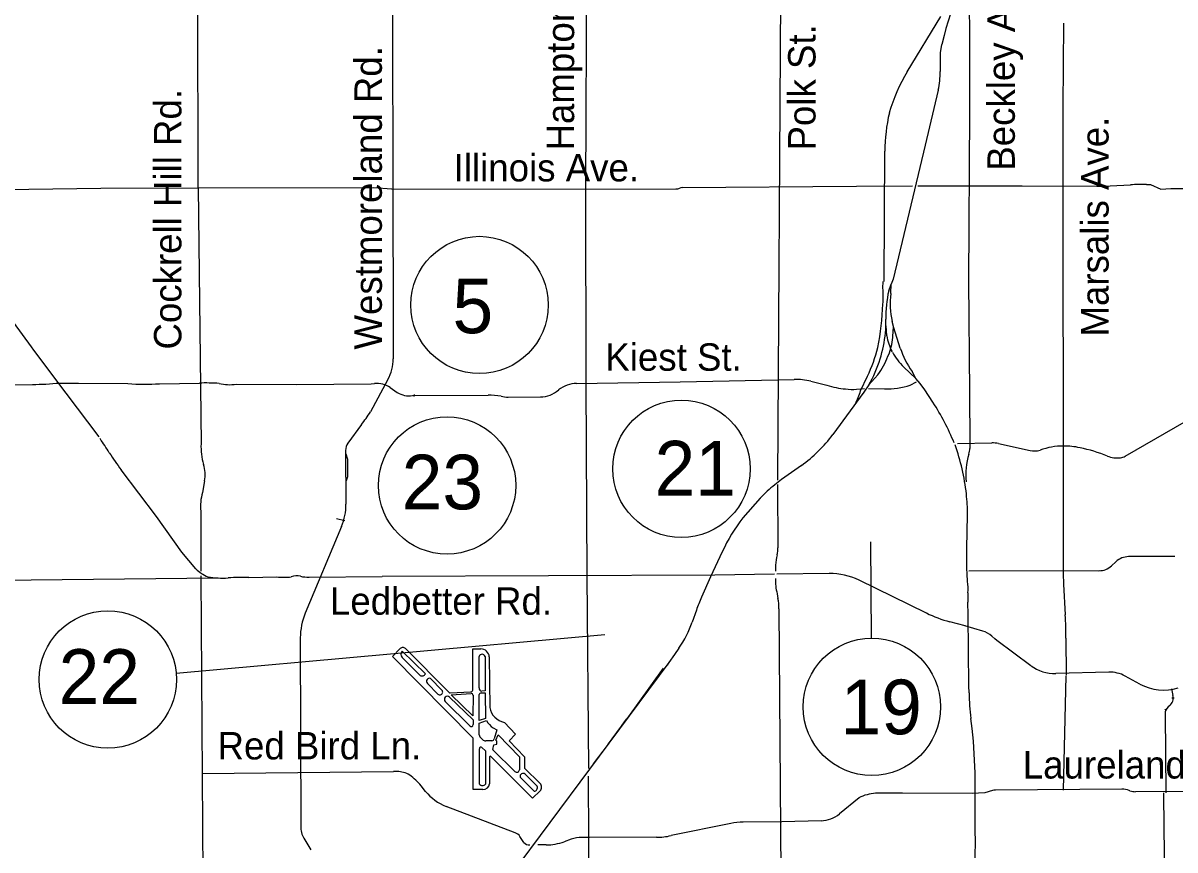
# Model space of a CAD drawing. Extents: x 105094 to 105814, y -291615 to -291123.
# Drawn here: x 105395.2 to 105446.1, y -291530.7 to -291494.1 of the extents above; entities that cross this region are included whole.
import ezdxf

# ---------------------------------------------------------------- set-up
doc = ezdxf.new("R2010")
doc.units = 0
doc.layers.add('G_BORDER', color=7, linetype='Continuous')
doc.layers.add('G_MAP', color=7, linetype='Continuous')

msp = doc.modelspace()

# ---------------------------------------------------------------- linework, layer by layer
at = {"layer": 'G_BORDER'}
for p, q in [((105432.632, -291517.07), (105432.669, -291521.335)), ((105420.896, -291521.192), (105401.969, -291522.889))]:
    msp.add_line(p, q, dxfattribs=at)
for centre in [(105415.362, -291506.606), (105424.284, -291513.846), (105413.931, -291514.582), (105398.946, -291523.16), (105432.696, -291524.37)]:
    msp.add_circle(centre, 3.035, dxfattribs=at)
at = {"layer": 'G_MAP'}
for p, q in [((105428.684, -291489.722), (105428.529, -291514.353)), ((105402.905, -291491.656), (105402.928, -291501.409)), ((105434.261, -291496.294), (105435.744, -291493.849)), ((105436.176, -291493.74), (105435.97, -291494.385)), ((105435.779, -291495.093), (105435.721, -291495.454)), ((105435.721, -291495.454), (105435.714, -291495.734)), ((105435.629, -291497.104), (105435.056, -291499.543)), ((105433.247, -291505.572), (105433.272, -291499.814)), ((105435.056, -291499.543), (105433.632, -291505.459)), ((105402.931, -291501.409), (105403.064, -291512.751)), ((105411.499, -291501.48), (105424.035, -291501.477)), ((105443.227, -291501.342), (105444.128, -291501.297)), ((105444.835, -291501.277), (105445.014, -291501.282)), ((105393.398, -291505.54), (105395.562, -291508.449)), ((105433.189, -291505.866), (105433.196, -291505.572)), ((105433.632, -291505.459), (105433.557, -291505.685)), ((105433.443, -291505.979), (105433.557, -291505.685)), ((105433.531, -291506.105), (105433.557, -291505.685)), ((105433.364, -291507.963), (105433.331, -291507.529)), ((105411.548, -291507.862), (105411.551, -291508.988)), ((105395.555, -291508.459), (105395.662, -291508.598)), ((105395.662, -291508.598), (105397.089, -291510.497)), ((105433.47, -291508.718), (105433.573, -291508.349)), ((105433.602, -291508.686), (105433.564, -291508.618)), ((105433.41, -291508.876), (105433.47, -291508.718)), ((105434.639, -291509.851), (105434.103, -291509.354)), ((105434.639, -291509.851), (105434.473, -291509.543)), ((105388.283, -291510.206), (105395.62, -291510.118)), ((105401.233, -291510.09), (105402.988, -291510.056)), ((105411.32, -291509.9), (105410.543, -291511.333)), ((105410.585, -291510.09), (105410.727, -291510.078)), ((105430.001, -291509.979), (105430.712, -291510.155)), ((105432.201, -291510.407), (105432.507, -291509.753)), ((105432.569, -291510.142), (105432.343, -291510.458)), ((105432.569, -291510.142), (105432.962, -291509.692)), ((105434.397, -291510.152), (105434.675, -291509.996)), ((105434.83, -291510.084), (105434.639, -291509.851)), ((105397.089, -291510.497), (105398.546, -291512.441)), ((105411.418, -291510.259), (105411.732, -291510.471)), ((105412.41, -291510.61), (105415.741, -291510.591)), ((105412.475, -291510.568), (105412.471, -291510.658)), ((105416.636, -291510.679), (105418.059, -291510.671)), ((105432.343, -291510.458), (105430.972, -291512.332)), ((105432.021, -291510.329), (105432.372, -291510.303)), ((105432.543, -291510.3), (105433.257, -291510.31)), ((105437.013, -291510.468), (105437.026, -291512.729)), ((105410.149, -291511.892), (105409.55, -291512.72)), ((105436.483, -291512.729), (105437.995, -291512.705)), ((105409.447, -291513.034), (105409.467, -291515.407)), ((105437.026, -291512.729), (105437.026, -291512.948)), ((105438.285, -291512.734), (105439.685, -291513.039)), ((105429.583, -291513.705), (105428.713, -291514.327)), ((105403.218, -291514.38), (105403.122, -291514.899)), ((105428.713, -291514.327), (105428.409, -291514.56)), ((105428.529, -291514.547), (105428.549, -291517.34)), ((105427.77, -291515.143), (105427.005, -291516.016)), ((105403.051, -291515.719), (105403.058, -291518.367)), ((105409.048, -291516.042), (105409.41, -291516.139)), ((105409.273, -291516.398), (105407.669, -291520.23)), ((105426.086, -291517.522), (105425.574, -291518.625)), ((105446.088, -291517.721), (105444.039, -291517.731)), ((105428.445, -291518.11), (105428.445, -291518.37)), ((105436.907, -291518.493), (105436.9, -291518.261)), ((105443.48, -291517.953), (105443.284, -291518.135)), ((105394.157, -291518.774), (105403.813, -291518.671)), ((105403.058, -291518.577), (105403.252, -291547.706)), ((105405.176, -291518.654), (105406.413, -291518.629)), ((105407.838, -291518.636), (105411.063, -291518.603)), ((105425.755, -291518.554), (105411.063, -291518.603)), ((105425.574, -291518.625), (105425.174, -291519.524)), ((105428.393, -291518.509), (105425.755, -291518.554)), ((105430.816, -291518.477), (105428.493, -291518.506)), ((105435.105, -291520.222), (105432.132, -291518.772)), ((105436.919, -291518.823), (105436.907, -291518.493)), ((105442.732, -291518.354), (105436.984, -291518.374)), ((105441.17, -291518.952), (105441.234, -291520.308)), ((105428.516, -291519.368), (105428.545, -291519.575)), ((105436.945, -291520.308), (105436.935, -291519.748)), ((105424.946, -291520.1), (105424.762, -291520.625)), ((105436.987, -291523.437), (105436.958, -291520.321)), ((105436.813, -291520.793), (105436.147, -291520.613)), ((105437.604, -291521.023), (105436.811, -291520.794)), ((105407.446, -291521.317), (105407.466, -291529.651)), ((105438.124, -291521.361), (105437.992, -291521.24)), ((105438.221, -291521.435), (105438.124, -291521.361)), ((105441.263, -291521.335), (105441.276, -291522.972)), ((105411.528, -291522.142), (105411.86, -291521.795)), ((105412.093, -291521.793), (105414.007, -291523.726)), ((105439.727, -291522.554), (105438.221, -291521.435)), ((105411.934, -291521.923), (105411.948, -291521.906)), ((105412.715, -291522.957), (105411.945, -291522.182)), ((105415.349, -291523.53), (105415.346, -291522.14)), ((105415.611, -291522.146), (105415.62, -291523.667)), ((105415.795, -291522.162), (105415.817, -291524.396)), ((105423.73, -291522.407), (105413.909, -291535.612)), ((105423.484, -291522.665), (105421.873, -291524.894)), ((105443.164, -291522.836), (105440.825, -291522.901)), ((105413.53, -291523.807), (105413.065, -291523.333)), ((105413.205, -291523.114), (105413.704, -291523.638)), ((105441.267, -291522.992), (105441.154, -291528.059)), ((105444.54, -291523.361), (105443.891, -291523.01)), ((105414.073, -291523.751), (105414.988, -291523.701)), ((105415.078, -291523.859), (105415.075, -291524.774)), ((105415.62, -291523.667), (105415.467, -291523.675)), ((105436.991, -291523.757), (105436.987, -291523.437)), ((105445.933, -291523.57), (105446, -291523.871)), ((105414.932, -291525.216), (105413.853, -291524.131)), ((105414.04, -291523.942), (105415.078, -291524.949)), ((105445.853, -291524.318), (105445.79, -291524.372)), ((105446.053, -291523.983), (105445.956, -291523.99)), ((105437.133, -291525.333), (105437.072, -291524.88)), ((105445.72, -291524.529), (105445.633, -291524.487)), ((105445.648, -291524.68), (105445.681, -291528.165)), ((105415.078, -291524.949), (105415.078, -291525.157)), ((105415.966, -291525.304), (105416.137, -291525.381)), ((105416.137, -291525.381), (105416.019, -291525.787)), ((105415.497, -291525.811), (105415.386, -291525.689)), ((105415.914, -291525.868), (105415.65, -291525.876)), ((105415.359, -291527.781), (105415.359, -291526.22)), ((105415.474, -291526.172), (105415.627, -291526.321)), ((105415.627, -291526.321), (105415.63, -291527.794)), ((105416.927, -291527.228), (105415.969, -291526.286)), ((105421.046, -291526.021), (105420.387, -291526.896)), ((105415.811, -291526.608), (105415.805, -291527.767)), ((105403.116, -291527.319), (105411.564, -291527.229)), ((105411.723, -291527.229), (105411.564, -291527.229)), ((105417.38, -291527.347), (105417.917, -291527.881)), ((105412.986, -291528.111), (105412.785, -291527.861)), ((105417.775, -291528.104), (105417.164, -291527.484)), ((105437.265, -291528.246), (105437.265, -291527.574)), ((105432.13, -291528.395), (105431.262, -291529.105)), ((105434.058, -291528.185), (105432.863, -291528.188)), ((105437.136, -291528.194), (105434.058, -291528.185)), ((105437.265, -291530.006), (105437.265, -291528.246)), ((105443.746, -291528.013), (105438.16, -291528.05)), ((105444.1, -291528.078), (105444.067, -291528.067)), ((105448.589, -291528.101), (105444.347, -291528.12)), ((105416.944, -291529.932), (105413.89, -291528.768)), ((105428.723, -291529.454), (105427.014, -291529.463)), ((105430.454, -291529.406), (105428.723, -291529.454)), ((105426.469, -291529.531), (105423.827, -291530.058)), ((105407.605, -291530.18), (105407.911, -291530.697)), ((105417.327, -291530.362), (105417.153, -291530.098)), ((105418.305, -291530.471), (105417.943, -291530.471)), ((105419.414, -291530.22), (105419.106, -291530.331)), ((105420.229, -291530.142), (105419.895, -291530.138)), ((105423.181, -291530.129), (105420.229, -291530.142))]:
    msp.add_line(p, q, dxfattribs=at)
for points in [[(105411.418, -291484.332), (105411.509, -291487.671), (105411.548, -291507.862)], [(105420.038, -291485.259), (105420.086, -291487.387), (105420.086, -291491.595), (105420.048, -291501.487), (105420.061, -291510.045), (105420.113, -291518.574), (105420.181, -291527.093)], [(105436.948, -291489.541), (105436.948, -291490.972), (105436.971, -291493.09), (105437.006, -291494.166), (105437.006, -291494.818), (105437.01, -291498.067), (105436.971, -291505.559), (105437.013, -291510.468)], [(105435.97, -291494.385), (105435.895, -291494.689), (105435.782, -291495.093)], [(105441.164, -291494.142), (105441.14, -291497.86), (105441.15, -291518.183)], [(105411.499, -291501.48), (105410.689, -291501.429), (105402.938, -291501.448), (105398.63, -291501.464), (105394.402, -291501.522), (105386.9, -291501.593)], [(105424.313, -291501.42), (105432.023, -291501.348), (105434.487, -291501.342)], [(105434.733, -291501.342), (105439.338, -291501.342), (105442.632, -291501.358)], [(105445.014, -291501.282), (105445.462, -291501.487), (105445.901, -291501.464)], [(105445.901, -291501.464), (105446.925, -291501.452), (105448.049, -291501.444)], [(105433.953, -291508.511), (105433.674, -291507.62), (105433.59, -291507.332)], [(105396.831, -291510.067), (105397.645, -291510.067), (105399.831, -291510.083)], [(105404.614, -291510.109), (105407.285, -291510.116), (105410.585, -291510.09)], [(105419.652, -291510.073), (105424.23, -291510), (105429.267, -291509.897)], [(105435.395, -291510.909), (105435.037, -291510.361), (105434.83, -291510.084)], [(105443.89, -291513.291), (105448.72, -291510.51), (105449.989, -291509.735)], [(105409.491, -291514.366), (105409.552, -291514.182), (105409.555, -291513.436), (105409.478, -291513.2)], [(105402.828, -291518.267), (105402.215, -291517.537), (105401.091, -291515.955), (105399.536, -291513.894)], [(105436.9, -291518.261), (105436.9, -291517.376), (105436.921, -291515.881)], [(105428.587, -291520.04), (105428.713, -291535.628), (105428.736, -291543.637), (105428.72, -291546.744)], [(105415.074, -291523.597), (105415.065, -291521.806), (105415.421, -291521.806)], [(105424.17, -291521.775), (105423.972, -291522.055), (105423.73, -291522.407), (105423.656, -291522.523)], [(105415.515, -291528.03), (105415.091, -291528.03), (105415.087, -291525.756), (105411.528, -291522.142)], [(105411.948, -291521.906), (105412.985, -291522.904), (105412.954, -291522.944)], [(105415.075, -291524.774), (105414.115, -291523.841), (105414.995, -291523.778)], [(105415.637, -291524.878), (105415.349, -291524.978), (105415.346, -291523.828)], [(105415.441, -291523.757), (105415.62, -291523.754), (105415.637, -291524.878)], [(105415.356, -291525.604), (105415.352, -291525.097), (105415.678, -291524.974)], [(105416.463, -291525.055), (105416.951, -291525.575), (105416.68, -291525.879), (105417.358, -291526.576), (105417.355, -291527.087), (105418.039, -291527.755)], [(105415.96, -291526.257), (105415.998, -291526.056), (105416.124, -291526.021), (105416.127, -291525.882), (105416.092, -291525.846), (105416.195, -291525.604)], [(105416.195, -291525.604), (105417.132, -291526.576), (105417.126, -291527.151)], [(105418.04, -291528.083), (105417.703, -291528.414), (105415.868, -291526.559)], [(105420.297, -291545.217), (105420.265, -291544.225), (105420.181, -291527.435)], [(105438.021, -291528.072), (105437.695, -291528.178), (105437.136, -291528.194)], [(105445.711, -291535.419), (105445.701, -291532.993), (105445.646, -291531.886), (105445.61, -291529.719), (105445.601, -291528.165)]]:
    msp.add_lwpolyline(points, dxfattribs=at)
for centre, radius, start, end in [((105447.982, -291496.012), 12.271, 178.7008, 181.2855), ((105440.56, -291500.113), 7.367, 148.7734, 164.2625), ((105432.488, -291496.364), 3.228, 346.7609, 1.3625), ((105440.758, -291499.824), 7.485, 166.8045, 179.9189), ((105424.038, -291500.988), 0.489, 269.6178, 291.7942), ((105424.315, -291501.639), 0.219, 90.6234, 115.9105), ((105442.781, -291495.888), 5.472, 268.4408, 274.6687), ((105444.685, -291508.719), 7.444, 88.8439, 94.292), ((105425.618, -291506.182), 7.578, 357.087, 2.3875), ((105438.781, -291507.17), 5.47, 167.4298, 180.689), ((105437.34, -291506.54), 3.833, 173.4908, 191.9344), ((105419.886, -291505.99), 13.312, 349.2107, 357.5159), ((105429.85, -291507.5), 3.472, 354.3975, 4.3771), ((105429.397, -291507.558), 4.251, 349.2674, 0.3861), ((105424.71, -291506.682), 8.672, 344.5535, 352.334), ((105435.404, -291507.692), 2.058, 187.5488, 207.7788), ((105425.894, -291506.66), 7.3, 334.9346, 345.55), ((105437.357, -291507.443), 3.567, 197.4174, 216.0568), ((105409.637, -291508.988), 1.914, 331.5403, 0.0101), ((105426.513, -291506.821), 6.907, 331.2632, 341.6793), ((105430.236, -291507.666), 3.396, 323.3824, 339.1343), ((105436.418, -291507.097), 3.233, 209.432, 224.2744), ((105395.438, -291495.763), 14.357, 270.7286, 275.4652), ((105400.586, -291498.341), 11.766, 266.3213, 273.1505), ((105403.228, -291522.098), 12.044, 86.9672, 91.14), ((105404.338, -291508.176), 1.953, 255.9652, 278.1126), ((105410.817, -291511.146), 1.072, 55.8818, 94.8346), ((105419.673, -291511.374), 1.301, 90.938, 128.5797), ((105429.324, -291512.72), 2.823, 76.1233, 91.1639), ((105431.866, -291506.525), 3.809, 252.3603, 265.02), ((105433.39, -291507.083), 3.229, 267.6362, 288.167), ((105412.253, -291509.652), 0.971, 237.539, 279.3173), ((105415.76, -291514.063), 3.472, 80.7583, 90.3095), ((105416.65, -291509.372), 1.307, 255.2579, 269.3639), ((105418.052, -291509.443), 1.229, 270.3001, 290.4566), ((105417.656, -291508.842), 1.936, 295.2478, 308.5319), ((105431.833, -291507.617), 2.719, 263.7139, 273.9614), ((105427.614, -291508.878), 4.835, 334.3285, 341.5711), ((105426.75, -291516.573), 10.336, 21.9726, 33.2322), ((105406.092, -291508.613), 5.217, 321.0516, 328.5656), ((105384.28, -291522.224), 17.307, 31.664, 34.1344), ((105409.987, -291513.036), 0.54, 144.1258, 179.7639), ((105426.002, -291508.694), 6.159, 305.5528, 323.8053), ((105438.015, -291513.977), 1.272, 77.7063, 90.902), ((105409.018, -291506.742), 11.877, 212.5849, 217.0228), ((105405.746, -291512.876), 2.685, 177.3279, 196.8598), ((105427.432, -291515.994), 9.499, 6.2854, 19.7309), ((105440.328, -291514.143), 3.478, 164.2154, 184.5783), ((105435.747, -291512.847), 1.283, 344.1791, 355.4858), ((105439.872, -291512.28), 0.781, 256.1122, 289.0947), ((105441.179, -291516.053), 3.211, 90.2318, 109.1124), ((105441.176, -291516.34), 3.498, 78.1706, 90.1563), ((105440.444, -291519.833), 7.067, 67.9135, 78.1671), ((105401.724, -291514.103), 1.52, 349.4871, 17.1218), ((105443.531, -291512.237), 1.132, 247.6973, 277.8604), ((105443.628, -291512.835), 0.526, 275.9221, 299.8681), ((105431.51, -291518.599), 5.092, 127.5147, 137.2643), ((105405.377, -291515.507), 2.336, 164.8993, 185.1997), ((105429.707, -291515.78), 7.214, 359.1969, 6.5775), ((105406.967, -291515.432), 2.5, 337.2751, 0.5684), ((105432.855, -291520.617), 7.443, 141.8157, 155.4232), ((105430.803, -291518.22), 2.36, 165.9588, 177.3396), ((105427.39, -291517.359), 1.159, 345.6001, 0.9081), ((105444.043, -291518.557), 0.826, 90.2854, 132.9841), ((105404.108, -291516.918), 1.86, 226.5115, 246.4272), ((105449.687, -291518.352), 8.539, 178.8649, 184.0257), ((105442.729, -291517.54), 0.814, 270.2071, 312.9887), ((105404.03, -291514.577), 4.1, 260.6501, 273.2682), ((105404.913, -291530.003), 11.352, 88.6714, 93.2762), ((105406.714, -291515.59), 3.054, 264.3433, 276.2411), ((105407.3, -291519.371), 0.787, 78.6655, 108.7984), ((105407.813, -291516.92), 1.716, 257.9405, 270.8348), ((105430.408, -291518.828), 1.968, 176.0781, 195.9399), ((105430.853, -291521.394), 2.917, 63.998, 90.7255), ((105434.526, -291519.194), 2.423, 356.629, 8.8163), ((105442.378, -291519.656), 5.443, 176.6374, 180.9703), ((105431.996, -291522.561), 7.467, 156.0015, 160.756), ((105427.493, -291519.904), 1.102, 352.9326, 17.3848), ((105410.332, -291521.344), 2.886, 157.306, 179.4689), ((105437.681, -291514.937), 5.879, 244.0098, 254.8703), ((105432.582, -291521.067), 8.686, 358.2315, 5.0126), ((105420.379, -291519.095), 4.643, 324.7453, 340.7534), ((105437.331, -291521.965), 0.981, 47.6506, 73.8558), ((105411.977, -291521.907), 0.162, 44.6974, 136.3213), ((105415.421, -291522.181), 0.375, 2.9287, 89.9675), ((105412.082, -291522.046), 0.192, 140.2138, 224.7896), ((105415.477, -291522.188), 0.14, 17.4842, 160.0694), ((105440.777, -291521.142), 1.759, 233.3902, 271.5724), ((105443.204, -291524.279), 1.443, 61.5641, 91.5771), ((105412.829, -291522.845), 0.16, 224.7655, 321.6949), ((105413.16, -291523.24), 0.133, 70.481, 224.2798), ((105445.592, -291521.415), 2.212, 241.5797, 286.5989), ((105413.617, -291523.722), 0.122, 223.958, 44.2114), ((105413.947, -291524.037), 0.133, 45.8052, 224.9535), ((105414.068, -291523.666), 0.0861, 224.7539, 273.0389), ((105414.982, -291523.608), 0.0931, 273.3806, 7.0742), ((105415, -291523.856), 0.0776, 357.2538, 94.0873), ((105415.464, -291523.557), 0.118, 166.9381, 271.6949), ((105415.451, -291523.869), 0.113, 94.7833, 158.8322), ((105446.179, -291523.66), 9.188, 180.6005, 187.6255), ((105445.549, -291523.971), 0.461, 311.105, 12.4948), ((105416.618, -291524.257), 0.813, 189.8593, 259.009), ((105446.064, -291524.685), 0.416, 131.1371, 179.2023), ((105399.89, -291509.635), 26.759, 322.2416, 325.2348), ((105414.993, -291525.156), 0.0851, 224.8113, 0), ((105416.471, -291524.573), 0.888, 206.8633, 235.3525), ((105406.847, -291528.247), 30.426, 1.2675, 5.4963), ((105415.474, -291525.61), 0.118, 177.1663, 221.8843), ((105415.644, -291525.678), 0.198, 222.224, 271.7562), ((105415.91, -291525.755), 0.113, 271.7849, 343.5206), ((105415.427, -291526.22), 0.0679, 45.603, 180.0047), ((105415.992, -291526.263), 0.0326, 169.471, 225.5678), ((105415.843, -291526.588), 0.0382, 50.4856, 211.7385), ((105411.722, -291528.312), 1.084, 58.975, 89.9981), ((105410.773, -291529.48), 2.582, 38.8269, 54.2777), ((105417.009, -291527.144), 0.117, 225.545, 356.8417), ((105417.288, -291527.44), 0.131, 45.1934, 199.4382), ((105415.5, -291527.677), 0.175, 216.3675, 318.1798), ((105415.515, -291527.738), 0.292, 270.1336, 354.2779), ((105417.762, -291527.939), 0.165, 274.345, 20.6052), ((105417.879, -291527.92), 0.229, 314.4843, 45.6737), ((105414.652, -291526.769), 2.139, 218.831, 249.1402), ((105432.989, -291530.039), 1.856, 93.9013, 117.5859), ((105438.163, -291528.508), 0.458, 90.3552, 108.0156), ((105443.753, -291528.952), 0.939, 70.4626, 90.4231), ((105444.344, -291527.39), 0.73, 250.5036, 270.2608), ((105426.963, -291531.282), 1.819, 88.3894, 105.7768), ((105430.417, -291528.072), 1.335, 271.5782, 309.2991), ((105408.469, -291529.67), 1.003, 178.908, 210.5826), ((105416.789, -291530.339), 0.435, 33.4792, 69.1557), ((105426.875, -291530.398), 10.397, 355.8901, 2.1583), ((105417.538, -291530.222), 0.253, 213.5041, 280.5213), ((105418.305, -291528.107), 2.364, 269.9988, 289.8226), ((105419.882, -291531.517), 1.379, 89.4506, 109.808), ((105423.275, -291528.013), 2.118, 267.4526, 285.0985)]:
    msp.add_arc(centre, radius, start, end, dxfattribs=at)

# ---------------------------------------------------------------- texts
at = {"layer": 'G_BORDER'}
for s, p in [('5', (105414.172, -291507.855)), ('21', (105423.099, -291515.029)), ('23', (105411.929, -291515.641)), ('22', (105396.773, -291524.239)), ('19', (105431.312, -291525.582))]:
    msp.add_text(s, height=2.416, dxfattribs=at).set_placement(p)
at = {"layer": 'G_MAP'}
for s, height, p in [('Hampton Rd.', 1.21107, (105419.546, -291499.777)), ('Beckley Ave.', 1.21107, (105439.014, -291500.67)), ('Polk St.', 1.2111, (105430.208, -291499.777)), ('Westmoreland Rd.', 1.21107, (105411.052, -291508.575)), ('Cockrell Hill Rd.', 1.21107, (105402.196, -291508.575)), ('Marsalis Ave.', 1.21107, (105443.155, -291508.001))]:
    msp.add_text(s, height=height, rotation=90, dxfattribs=at).set_placement(p)
for s, height, p in [('Illinois Ave.', 1.21107, (105414.223, -291501.143)), ('Kiest St.', 1.2111, (105420.922, -291509.513)), ('Ledbetter Rd.', 1.21107, (105408.759, -291520.3)), ('Red Bird Ln.', 1.21107, (105403.791, -291526.695)), ('Laureland Rd.', 1.21107, (105439.365, -291527.538))]:
    msp.add_text(s, height=height, dxfattribs=at).set_placement(p)

doc.saveas('drawing.dxf')
